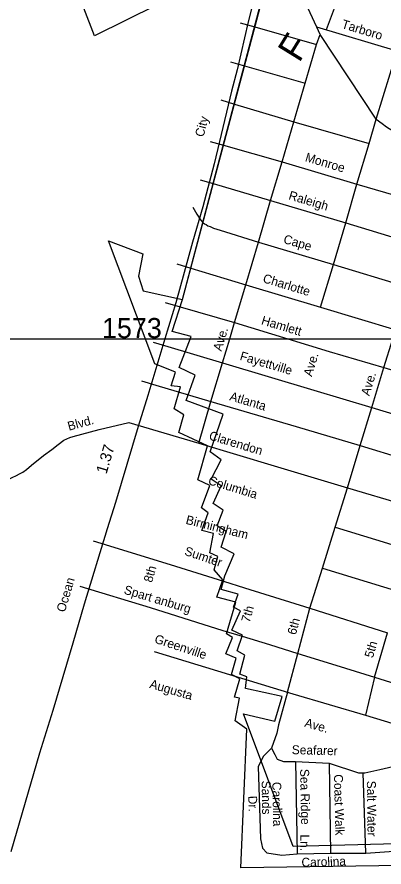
# Model space of a CAD drawing. Extents: x 1945482 to 2853149, y 66427 to 1015778.
# Drawn here: x 2329928 to 2332623, y 101482 to 107724 of the extents above; entities that cross this region are included whole.
import ezdxf

# ---------------------------------------------------------------- set-up
doc = ezdxf.new("R2010")
doc.units = 0
for name, color, linetype in [('Old_Level_10', 7, 'Continuous'), ('Old_Level_11', 7, 'Continuous'), ('Old_Level_17', 7, 'Continuous'), ('Old_Level_22', 7, 'Continuous'), ('Old_Level_25', 7, 'Continuous'), ('Old_Level_32', 7, 'Continuous'), ('Old_Level_35', 7, 'Continuous'), ('Old_Level_48', 7, 'Continuous'), ('Old_Level_49', 7, 'Continuous'), ('Old_Level_8', 7, 'Continuous')]:
    doc.layers.add(name, color=color, linetype=linetype)

msp = doc.modelspace()

# ---------------------------------------------------------------- linework, layer by layer
at = {"layer": 'Old_Level_25'}
msp.add_lwpolyline([(2323249.7, 105360.7), (2336452.5, 105360.7)], dxfattribs=at)
at = {"layer": 'Old_Level_32'}
msp.add_lwpolyline([(2331702.9, 107997.6), (2331624.7, 107688.3), (2331543.7, 107337.5), (2331503.1, 107179.4), (2331416, 106810.4), (2331375.5, 106646.2), (2331292.7, 106331.3), (2331215.5, 106071.5), (2331093.2, 105625.3), (2331014.2, 105359.8), (2330976.3, 105239.2), (2330888.1, 104943.7), (2330818.5, 104717.7), (2330650, 104158.7), (2330589.2, 103966.1), (2330421.5, 103411.1), (2330338.7, 103124.9), (2330190, 102631.6), (2330094, 102319.1), (2329965.1, 101879.9), (2329882, 101594.1)], dxfattribs=at)
at = {"layer": 'Old_Level_35'}
for p, q in [((2331566, 107682.6), (2331674.5, 107651.7)), ((2331674.5, 107651.7), (2332128, 107522.3)), ((2332155, 107596.6), (2332130.5, 107650.4)), ((2332718.5, 107472.4), (2332130.5, 107650.4)), ((2332128, 107522.3), (2332155, 107596.6)), ((2332565.8, 106974.7), (2332155, 107596.6)), ((2332045, 107239.4), (2332128, 107522.3)), ((2332565.8, 106974.7), (2332718.5, 107472.4)), ((2331495, 107393.9), (2331598.4, 107364.9)), ((2331598.4, 107364.9), (2332045, 107239.4)), ((2331961.7, 106954.5), (2332045, 107239.4)), ((2331424, 107115.1), (2331524.1, 107085.2)), ((2331524.1, 107085.2), (2331961.7, 106954.5)), ((2331874.9, 106659.6), (2331961.7, 106954.5)), ((2331961.7, 106954.5), (2332513.5, 106794.1)), ((2332513.5, 106794.1), (2332565.8, 106974.7)), ((2331345.1, 106810), (2331443.6, 106782.1)), ((2331443.6, 106782.1), (2331874.9, 106659.6)), ((2332422.8, 106497.1), (2332513.5, 106794.1)), ((2331789.9, 106376.6), (2331874.9, 106659.6)), ((2331874.9, 106659.6), (2332422.8, 106497.1)), ((2331271.8, 106529.2), (2331368.8, 106500.6)), ((2331368.8, 106500.6), (2331789.9, 106376.6)), ((2332341.5, 106212.3), (2332422.8, 106497.1)), ((2332422.8, 106497.1), (2332978.4, 106332.9)), ((2331700.8, 106071.5), (2331789.9, 106376.6)), ((2331789.9, 106376.6), (2332341.5, 106212.3)), ((2332250.8, 105907.1), (2332341.5, 106212.3)), ((2332341.5, 106212.3), (2332893.6, 106045.7)), ((2331608.1, 105758.6), (2331700.8, 106071.5)), ((2331700.8, 106071.5), (2332250.8, 105907.1)), ((2331100.6, 105911.3), (2331204, 105880.2)), ((2331204, 105880.2), (2331608.1, 105758.6)), ((2332155.9, 105594.2), (2332250.8, 105907.1)), ((2332250.8, 105907.1), (2332800.6, 105740.7)), ((2331524.9, 105479.7), (2331608.1, 105758.6)), ((2331608.1, 105758.6), (2332155.9, 105594.2)), ((2331015.3, 105628.3), (2331126.1, 105596)), ((2331126.1, 105596), (2331524.9, 105479.7)), ((2332155.9, 105594.2), (2332709.9, 105427.6)), ((2331489.9, 105360.7), (2331524.9, 105479.7)), ((2331524.9, 105479.7), (2331916.6, 105360.7)), ((2330928.3, 105337.3), (2331036.1, 105305.1)), ((2331036.1, 105305.1), (2331438.1, 105184.8)), ((2331438.1, 105184.8), (2331489.9, 105360.7)), ((2332620.8, 105149.1), (2332688.5, 105360.7)), ((2331350.9, 104899.7), (2331438.1, 105184.8)), ((2332533.9, 104855.8), (2332620.8, 105149.1)), ((2332620.8, 105149.1), (2333176.8, 104982.6)), ((2330841.4, 105052.6), (2330948.1, 105020.6)), ((2330948.1, 105020.6), (2331350.9, 104899.7)), ((2331262.2, 104594.6), (2331350.9, 104899.7)), ((2332446.7, 104576.7), (2332533.9, 104855.8)), ((2332533.9, 104855.8), (2333087.9, 104689.6)), ((2330748.5, 104745.3), (2330857, 104713.5)), ((2330857, 104713.5), (2331262.2, 104594.6)), ((2332353.9, 104267.8), (2332446.7, 104576.7)), ((2332446.7, 104576.7), (2333006.7, 104408.7)), ((2332265, 103976.7), (2332353.9, 104267.8)), ((2332353.9, 104267.8), (2332912, 104099.4)), ((2332172.1, 103677.7), (2332265, 103976.7)), ((2332265, 103976.7), (2332825, 103806.5)), ((2332079.3, 103382.9), (2332172.1, 103677.7)), ((2332172.1, 103677.7), (2332738.2, 103503.4)), ((2331990.7, 103049.9), (2332079.3, 103382.9)), ((2332079.3, 103382.9), (2332647.3, 103202.5)), ((2332552.8, 102877.4), (2332647.3, 103202.5)), ((2331913.8, 102766.2), (2331990.7, 103049.9))]:
    msp.add_line(p, q, dxfattribs=at)
for points in [[(2332130.5, 107650.4), (2331952.4, 108030.7), (2331727.7, 108284.4)], [(2332325.8, 108021.8), (2332300.3, 107907.3), (2332199.1, 107629.7)], [(2332565.8, 106974.7), (2332608.2, 106941.3), (2332639.9, 106918.2), (2332660.1, 106904.9), (2332692.7, 106886.2), (2332732, 106863.4), (2332779.4, 106834.8), (2332847.6, 106795.8), (2332968.4, 106728.7)], [(2331220, 106328.9), (2331248.6, 106277.2), (2331262.7, 106253.1), (2331275.2, 106235.2), (2331293.1, 106215.6)], [(2331293.1, 106215.6), (2331293.4, 106215.3), (2331305.3, 106205.5), (2331317.7, 106199.8), (2331329.5, 106191.7), (2331345.8, 106186.1), (2331369.9, 106174.3), (2331420, 106158.9), (2331700.8, 106071.5)], [(2331916.6, 105360.7), (2332219.6, 105268.8), (2332620.8, 105149.1)], [(2331438.1, 105184.8), (2332108.4, 104983.4), (2332533.9, 104855.8)], [(2331350.9, 104899.7), (2331977.2, 104716), (2332446.7, 104576.7)], [(2329271, 104084.1), (2329584, 104213.3), (2329802.9, 104303.4), (2329838.8, 104317.9), (2329868.8, 104330.2), (2329891.3, 104342), (2329924.6, 104356.7), (2329946.1, 104369.1), (2329970.2, 104381.2), (2329998, 104401.6), (2330034.2, 104431.9), (2330122.9, 104503.1), (2330182.6, 104547.4), (2330229.4, 104583.7), (2330271.7, 104616.6), (2330293.7, 104626.6), (2330315.6, 104637), (2330341.6, 104643.3), (2330530.9, 104695.1), (2330748.5, 104745.3)], [(2331262.2, 104594.6), (2331816.2, 104428.4), (2332353.9, 104267.8)], [(2330487.6, 103878.4), (2331051.5, 103704.4), (2331443.6, 103580.8)], [(2331443.6, 103580.8), (2331599.5, 103531.7), (2332079.3, 103382.9)], [(2330389.2, 103545.3), (2330904.7, 103388.4), (2331438.8, 103220.1), (2331581.5, 103176.6)], [(2331581.5, 103176.6), (2331782, 103115.5), (2331990.7, 103049.9)], [(2330935.6, 103064), (2331953.4, 102754.2), (2332486.9, 102597.1), (2333034.9, 102431.6), (2333577.7, 102266.1), (2334161.7, 102114.1)], [(2331990.7, 103049.9), (2332269.4, 102964.7), (2332552.8, 102877.4)], [(2332552.8, 102877.4), (2332486.9, 102597.1)], [(2332552.8, 102877.4), (2332827.7, 102790.5), (2333100.5, 102707)], [(2331913.8, 102766.2), (2331848.2, 102525), (2331835.5, 102465.6), (2331797.4, 102355.2), (2331738, 102295.8), (2331699.8, 102219.4), (2331716.8, 101688.9), (2331729.5, 101621), (2331763.4, 101587.1), (2331873.7, 101570.1), (2331984, 101578.6), (2332229.9, 101582.8), (2332488.6, 101582.8), (2332730.4, 101599.8), (2332976.4, 101599.8), (2333235.1, 101604), (2333481, 101612.5), (2333926.4, 101621), (2334237.6, 101616.8), (2334324.2, 101594)], [(2331797.4, 102355.2), (2331820.3, 102308.5), (2331837.2, 102274.6), (2331883.9, 102257.6), (2331972.9, 102257.6), (2332218.9, 102244.9), (2332435.2, 102172.7), (2332481.9, 102172.7), (2332592.1, 102198.2), (2332719.4, 102227.9), (2332922.9, 102236.4), (2332973.8, 102206.7), (2333253.7, 102075.1), (2333503.9, 101947.8), (2333860.2, 101773.8), (2333898.4, 101744.1), (2333923.8, 101688.9), (2333926.4, 101621)], [(2331972.9, 102257.6), (2331984, 101578.6)], [(2332218.9, 102244.9), (2332229.9, 101582.8)], [(2332488.6, 101582.8), (2332468.7, 102172.7)]]:
    msp.add_lwpolyline(points, dxfattribs=at)
at = {"layer": 'Old_Level_48'}
msp.add_lwpolyline([(2334135.9, 101690.1), (2331955.4, 101631.5), (2331590.7, 102608), (2331821, 102553.1), (2331875.9, 102733.3), (2331605.5, 102792.7), (2331616.1, 102879.1), (2331563.3, 102897.1), (2331601.8, 103038.6), (2331544.6, 103068.4), (2331584, 103184), (2331506.5, 103220.9), (2331568.9, 103363.5), (2331517.9, 103389.5), (2331552.1, 103484.8), (2331426.7, 103519.9), (2331454.7, 103621), (2331521.9, 103781.6), (2331426.4, 103831.5), (2331463.1, 103945.5), (2331397.1, 103988.3), (2331441.1, 104102.3), (2331367.7, 104152.2), (2331426.4, 104280.5), (2331353, 104330.4), (2331426.4, 104472.9), (2331345.7, 104530), (2331441.1, 104807.9), (2331169.4, 104907.7), (2331235.5, 105093), (2331118, 105150), (2331206.2, 105378.1), (2331066.6, 105413.7), (2331143, 105650.7), (2331813.7, 108175.7)], dxfattribs=at)
at = {"layer": 'Old_Level_49'}
for points in [[(2331649.5, 108157.8), (2330497.9, 107585.9), (2330352.2, 107963.5)], [(2334108.1, 101513.1), (2331571.6, 101475.2), (2331616.3, 102493.4), (2331529.2, 102555.9), (2331560.5, 102721.2), (2331524.8, 102730.1), (2331564.9, 102864.1), (2331502.5, 102895.3), (2331538.2, 103015.9), (2331462.3, 103047.2), (2331511.4, 103167.8), (2331466.8, 103194.6), (2331533.7, 103426.8), (2331395.3, 103462.5), (2331440, 103592), (2331375.3, 103663.5), (2331402, 103761.7), (2331344, 103788.5), (2331370.8, 103931.4), (2331286, 103953.8), (2331330.6, 104083.3), (2331281.5, 104119), (2331344, 104284.2), (2331254.7, 104324.4), (2331326.2, 104574.5), (2331116.4, 104672.8), (2331152.1, 104802.3), (2331082.9, 104847), (2331127.5, 105007.7), (2331060.6, 105016.7), (2331091.8, 105114.9), (2330940.1, 105177.4), (2330600.8, 106079.6), (2330850.8, 105985.8), (2330819.6, 105820.5), (2330855.3, 105713.4), (2331143, 105650.7), (2331791, 108107.9)]]:
    msp.add_lwpolyline(points, dxfattribs=at)

# ---------------------------------------------------------------- texts
at = {"layer": 'Old_Level_10'}
for s, height, rotation, p in [('Tarboro', 65.62, 342.94943, (2332306.3, 107644.7)), ('Monroe', 65.62, 343.47727, (2332039, 106666.5)), ('Raleigh', 65.62, 343.42923, (2331917.6, 106386.5)), ('Cape', 65.62, 343.62317, (2331879.2, 106065.3)), ('Charlotte', 65.62, 343.10807, (2331728.2, 105777.7)), ('Hamlett', 65.62, 343.2798, (2331716.9, 105468.7)), ('Ave.', 65.62, 73.21225, (2331428.4, 105266.3)), ('Fayettville', 65.617, 343.46582, (2331559.6, 105207.1)), ('Ave.', 65.62, 73.21225, (2332092.5, 105079.5)), ('Ave.', 65.62, 73.21225, (2332515.1, 104937.7)), ('Atlanta', 65.62, 343.31177, (2331483.9, 104911.2)), ('Blvd.', 65.62, 15.29729, (2330309.6, 104685.6)), ('Clarendon', 65.62, 343.1885, (2331332.3, 104622.7)), ('Columbia', 65.62, 343.01649, (2331326.9, 104293.8)), ('Birmingham', 65.62, 345.90469, (2331162.7, 104003)), ('Sumter', 65.62, 341.24008, (2331152.7, 103775.6)), ('8th', 65.62, 73.93401, (2330919.2, 103566.8)), ('Spart anburg', 65.617, 343.32272, (2330708.2, 103490.3)), ('7th', 65.62, 74.23248, (2331635.8, 103272.9)), ('6th', 65.62, 75.10035, (2331975.1, 103182.7)), ('Greenville', 65.62, 341.70464, (2330932.4, 103130.3)), ('5th', 65.62, 73.78839, (2332541, 103013.1)), ('Augusta', 65.62, 343.49117, (2330896.9, 102799)), ('Ave.', 65.62, 344.18864, (2332034.7, 102513.7)), ('Seafarer', 65.62, 358.51178, (2331944.9, 102311.1)), ('Sea Ridge', 65.62, 271.01062, (2332006.9, 102202.1)), ('Coast Walk', 65.62, 271.39978, (2332255.2, 102162.5)), ('Sands', 65.62, 270.89063, (2331724.3, 102115.8)), ('Carolina', 65.62, 271.18528, (2331802.4, 102106.5)), ('Salt Water', 65.62, 270.76073, (2332497, 102115)), ('Dr.', 65.62, 272.21623, (2331625, 102004)), ('Ln.', 65.62, 270.53356, (2332008, 101720.7)), ('Carolina', 65.62, 1.79157, (2332017.7, 101483.1))]:
    msp.add_text(s, height=height, rotation=rotation, dxfattribs=at).set_placement(p)
at = {"layer": 'Old_Level_11'}
for s, rotation, p in [('City', 75.70454, (2331297.5, 106838.7)), ('Ocean', 73.41575, (2330279.3, 103348.7))]:
    msp.add_text(s, height=65.62, rotation=rotation, dxfattribs=at).set_placement(p)
at = {"layer": 'Old_Level_17'}
msp.add_text('1.37', height=82.02, rotation=73.44544, dxfattribs=at).set_placement((2330585.1, 104364.1))
at = {"layer": 'Old_Level_22'}
msp.add_text('F', height=196.8, rotation=58.24887, dxfattribs=at).set_placement((2332000, 107382.6))
at = {"layer": 'Old_Level_8'}
msp.add_text('1573', height=147.64, dxfattribs=at).set_placement((2330551.9, 105366.3))

doc.saveas('drawing.dxf')
